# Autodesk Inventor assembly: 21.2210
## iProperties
Created: 2012-07
Part Number: 21.2210
Document SubType Name: Assembly
Designer: Administrator
Description: STRENGTHENING ELEMENT 30X60
Mass: 344.411 g
Surface Area: 1640.71 cm^2
Volume: 113.969 cm^3
Density: 3.02198 g/cm^3
Author: Administrator
